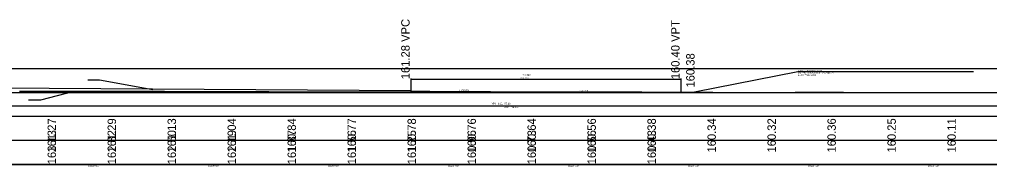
# Model space of a CAD drawing. Extents: x 2126510 to 2136144, y 865066 to 868066.
# Drawn here: x 2130187 to 2130996, y 866612 to 866735 of the extents above; entities that cross this region are included whole.
import ezdxf

# ---------------------------------------------------------------- set-up
doc = ezdxf.new("R2010")
doc.units = 0
for name, color, linetype in [('RD_EX_GuardRail', 7, 'Continuous'), ('RD_EX_H2O', 7, 'Continuous'), ('RD_EX_Misc', 7, 'Continuous')]:
    doc.layers.add(name, color=color, linetype=linetype)

msp = doc.modelspace()

# ---------------------------------------------------------------- linework, layer by layer
at = {"layer": 'RD_EX_GuardRail'}
for p, q in [((2131097.7, 866693.9), (2126517.45, 866693.9)), ((2131097.7, 866673.9), (2129000.13, 866673.9)), ((2131097.7, 866653.9), (2126517.45, 866653.9)), ((2131097.7, 866633.9), (2126517.45, 866633.9)), ((2131097.7, 866613.9), (2126517.45, 866613.9))]:
    msp.add_line(p, q, dxfattribs=at)
at = {"layer": 'RD_EX_H2O'}
for points in [[(2130187.19, 866675.18), (2130188.19, 866675.19), (2130189.19, 866675.19), (2130190.19, 866675.19), (2130191.19, 866675.18), (2130192.19, 866675.18), (2130193.19, 866675.18), (2130194.19, 866675.17), (2130195.19, 866675.17), (2130196.19, 866675.17), (2130197.19, 866675.17), (2130198.19, 866675.17), (2130199.19, 866675.17), (2130200.19, 866675.16), (2130201.19, 866675.16), (2130202.19, 866675.16), (2130203.19, 866675.16), (2130204.19, 866675.16), (2130205.19, 866675.16), (2130206.19, 866675.16), (2130207.19, 866675.16), (2130208.19, 866675.16), (2130209.19, 866675.16), (2130210.19, 866675.16), (2130211.19, 866675.16), (2130212.19, 866675.17), (2130213.19, 866675.17), (2130214.19, 866675.17), (2130215.19, 866675.17), (2130216.19, 866675.17), (2130217.19, 866675.17), (2130218.19, 866675.17), (2130219.19, 866675.17), (2130220.19, 866675.17), (2130221.19, 866675.17), (2130222.19, 866675.17), (2130223.19, 866675.17), (2130224.19, 866675.17), (2130225.19, 866675.17), (2130226.19, 866675.17), (2130227.19, 866675.18), (2130228.19, 866675.18), (2130229.19, 866675.18), (2130230.19, 866675.18), (2130231.19, 866675.18), (2130232.19, 866675.18)], [(2130232.19, 866675.18), (2130233.19, 866675.18), (2130234.19, 866675.18), (2130235.19, 866675.19), (2130236.19, 866675.19), (2130237.19, 866675.19), (2130238.19, 866675.19), (2130239.19, 866675.19), (2130240.19, 866675.19), (2130241.19, 866675.19), (2130242.19, 866675.2), (2130243.19, 866675.2), (2130244.19, 866675.2), (2130245.19, 866675.2), (2130246.19, 866675.2), (2130247.19, 866675.2), (2130248.19, 866675.21), (2130249.19, 866675.21), (2130250.19, 866675.21), (2130251.19, 866675.21), (2130252.19, 866675.21), (2130253.19, 866675.21), (2130254.19, 866675.21), (2130255.19, 866675.21), (2130256.19, 866675.21), (2130257.19, 866675.21), (2130258.19, 866675.21), (2130259.19, 866675.21), (2130260.19, 866675.21), (2130261.19, 866675.2), (2130262.19, 866675.2), (2130263.19, 866675.2), (2130264.19, 866675.2), (2130265.19, 866675.2), (2130266.19, 866675.2), (2130267.19, 866675.2), (2130268.19, 866675.2), (2130269.19, 866675.19), (2130270.19, 866675.19), (2130271.19, 866675.19), (2130272.19, 866675.19), (2130273.19, 866675.19), (2130274.19, 866675.19), (2130275.19, 866675.19), (2130276.19, 866675.18), (2130277.19, 866675.18), (2130278.19, 866675.18), (2130279.19, 866675.18), (2130280.19, 866675.18), (2130281.19, 866675.18), (2130282.19, 866675.17), (2130283.19, 866675.17), (2130284.19, 866675.17), (2130285.19, 866675.17), (2130286.19, 866675.17), (2130287.19, 866675.17), (2130288.19, 866675.17), (2130289.19, 866675.16), (2130290.19, 866675.16), (2130291.19, 866675.16), (2130292.19, 866675.16), (2130293.19, 866675.16), (2130294.19, 866675.16), (2130295.19, 866675.15), (2130296.19, 866675.15), (2130297.19, 866675.15), (2130298.19, 866675.15), (2130299.19, 866675.14), (2130300.19, 866675.14), (2130301.19, 866675.14), (2130302.19, 866675.13), (2130303.19, 866675.13), (2130304.19, 866675.12), (2130305.19, 866675.11), (2130306.19, 866675.1), (2130307.19, 866675.1), (2130308.19, 866675.09), (2130309.19, 866675.08), (2130310.19, 866675.08), (2130311.19, 866675.07), (2130312.19, 866675.06), (2130313.19, 866675.06), (2130314.19, 866675.05), (2130315.19, 866675.05), (2130316.19, 866675.04), (2130317.19, 866675.04), (2130318.19, 866675.04), (2130319.19, 866675.04), (2130320.19, 866675.04), (2130321.19, 866675.03), (2130322.19, 866675.03), (2130323.19, 866675.03), (2130324.19, 866675.03), (2130325.19, 866675.03), (2130326.19, 866675.03), (2130327.19, 866675.03), (2130328.19, 866675.02), (2130329.19, 866675.02), (2130330.19, 866675.02), (2130331.19, 866675.02), (2130332.19, 866675.02)], [(2130332.19, 866675.02), (2130333.19, 866675.02), (2130334.19, 866675.02), (2130335.19, 866675.02), (2130336.19, 866675.02), (2130337.19, 866675.02), (2130338.19, 866675.02), (2130339.19, 866675.02), (2130340.19, 866675.02), (2130341.19, 866675.02), (2130342.19, 866675.02), (2130343.19, 866675.02), (2130344.19, 866675.02), (2130345.19, 866675.02), (2130346.19, 866675.01), (2130347.19, 866675.01), (2130348.19, 866675.01), (2130349.19, 866675.01), (2130350.19, 866675.01), (2130351.19, 866675.01), (2130352.19, 866675.01), (2130353.19, 866675.01), (2130354.19, 866675.01), (2130355.19, 866675.01), (2130356.19, 866675), (2130357.19, 866675), (2130358.19, 866674.99), (2130359.19, 866674.99), (2130360.19, 866674.98), (2130361.19, 866674.98), (2130362.19, 866674.97), (2130363.19, 866674.97), (2130364.19, 866674.96), (2130365.19, 866674.96), (2130366.19, 866674.95), (2130367.19, 866674.95), (2130368.19, 866674.94), (2130369.19, 866674.94), (2130370.19, 866674.93), (2130371.19, 866674.93), (2130372.19, 866674.92), (2130373.19, 866674.92), (2130374.19, 866674.91), (2130375.19, 866674.91), (2130376.19, 866674.9), (2130377.19, 866674.9), (2130378.19, 866674.89), (2130379.19, 866674.89), (2130380.19, 866674.88), (2130381.19, 866674.88), (2130382.19, 866674.87), (2130383.19, 866674.87), (2130384.19, 866674.86), (2130385.19, 866674.86), (2130386.19, 866674.85), (2130387.19, 866674.85), (2130388.19, 866674.84), (2130389.19, 866674.84), (2130390.19, 866674.83), (2130391.19, 866674.83), (2130392.19, 866674.82), (2130393.19, 866674.82), (2130394.19, 866674.81), (2130395.19, 866674.81), (2130396.19, 866674.8), (2130397.19, 866674.8), (2130398.19, 866674.8), (2130399.19, 866674.8), (2130400.19, 866674.79), (2130401.19, 866674.79), (2130402.19, 866674.79), (2130403.19, 866674.79), (2130404.19, 866674.79), (2130405.19, 866674.78), (2130406.19, 866674.78), (2130407.19, 866674.78), (2130408.19, 866674.78), (2130409.19, 866674.77), (2130410.19, 866674.77), (2130411.19, 866674.77), (2130412.19, 866674.77), (2130413.19, 866674.76), (2130414.19, 866674.76), (2130415.19, 866674.76), (2130416.19, 866674.76), (2130417.19, 866674.75), (2130418.19, 866674.75), (2130419.19, 866674.75), (2130420.19, 866674.74), (2130421.19, 866674.74), (2130422.19, 866674.74), (2130423.19, 866674.73), (2130424.19, 866674.73), (2130425.19, 866674.73), (2130426.19, 866674.72), (2130427.19, 866674.72), (2130428.19, 866674.72), (2130429.19, 866674.71), (2130430.19, 866674.71), (2130431.19, 866674.71), (2130432.19, 866674.7)], [(2130432.19, 866674.7), (2130433.19, 866674.7), (2130434.19, 866674.7), (2130435.19, 866674.7), (2130436.19, 866674.7), (2130437.19, 866674.7), (2130438.19, 866674.7), (2130439.19, 866674.7), (2130440.19, 866674.7), (2130441.19, 866674.7), (2130442.19, 866674.69), (2130443.19, 866674.69), (2130444.19, 866674.69), (2130445.19, 866674.69), (2130446.19, 866674.69), (2130447.19, 866674.69), (2130448.19, 866674.69), (2130449.19, 866674.69), (2130450.19, 866674.69), (2130451.19, 866674.69), (2130452.19, 866674.69), (2130453.19, 866674.69), (2130454.19, 866674.68), (2130455.19, 866674.68), (2130456.19, 866674.68), (2130457.19, 866674.68), (2130458.19, 866674.68), (2130459.19, 866674.68), (2130460.19, 866674.68), (2130461.19, 866674.68), (2130462.19, 866674.68), (2130463.19, 866674.68), (2130464.19, 866674.67), (2130465.19, 866674.67), (2130466.19, 866674.67), (2130467.19, 866674.67), (2130468.19, 866674.67), (2130469.19, 866674.67), (2130470.19, 866674.67), (2130471.19, 866674.67), (2130472.19, 866674.67), (2130473.19, 866674.67), (2130474.19, 866674.67), (2130475.19, 866674.67), (2130476.19, 866674.67), (2130477.19, 866674.67), (2130478.19, 866674.67), (2130479.19, 866674.67), (2130480.19, 866674.67), (2130481.19, 866674.67), (2130482.19, 866674.67), (2130483.19, 866674.67), (2130484.19, 866674.68), (2130485.19, 866674.68), (2130486.19, 866674.68), (2130487.19, 866674.68), (2130488.19, 866674.68), (2130489.19, 866674.68), (2130490.19, 866674.68), (2130491.19, 866674.68), (2130492.19, 866674.68), (2130493.19, 866674.68), (2130494.19, 866674.68), (2130495.19, 866674.68), (2130496.19, 866674.68), (2130497.19, 866674.68), (2130498.19, 866674.68), (2130499.19, 866674.68), (2130500.19, 866674.68), (2130501.19, 866674.68), (2130502.19, 866674.68), (2130503.19, 866674.68), (2130504.19, 866674.68), (2130505.19, 866674.68), (2130506.19, 866674.68), (2130507.19, 866674.68), (2130508.19, 866674.68), (2130509.19, 866674.68), (2130510.19, 866674.68), (2130511.19, 866674.68), (2130512.19, 866674.68), (2130513.19, 866674.68), (2130514.19, 866674.68), (2130515.19, 866674.69), (2130516.19, 866674.69), (2130517.19, 866674.69), (2130518.19, 866674.69), (2130519.19, 866674.69), (2130520.19, 866674.69), (2130521.19, 866674.69), (2130522.19, 866674.69), (2130523.19, 866674.69), (2130524.19, 866674.69), (2130525.19, 866674.69), (2130526.19, 866674.69), (2130527.19, 866674.69), (2130528.19, 866674.69), (2130529.19, 866674.69), (2130530.19, 866674.69), (2130531.19, 866674.69), (2130532.19, 866674.69)], [(2130532.19, 866674.69), (2130533.19, 866674.69), (2130534.19, 866674.69), (2130535.19, 866674.69), (2130536.19, 866674.69), (2130537.19, 866674.69), (2130538.19, 866674.69), (2130539.19, 866674.7), (2130540.19, 866674.7), (2130541.19, 866674.7), (2130542.19, 866674.7), (2130543.19, 866674.7), (2130544.19, 866674.7), (2130545.19, 866674.7), (2130546.19, 866674.7), (2130547.19, 866674.7), (2130548.19, 866674.7), (2130549.19, 866674.7), (2130550.19, 866674.7), (2130551.19, 866674.7), (2130552.19, 866674.69), (2130553.19, 866674.69), (2130554.19, 866674.69), (2130555.19, 866674.69), (2130556.19, 866674.69), (2130557.19, 866674.68), (2130558.19, 866674.68), (2130559.19, 866674.68), (2130560.19, 866674.68), (2130561.19, 866674.68), (2130562.19, 866674.68), (2130563.19, 866674.67), (2130564.19, 866674.67), (2130565.19, 866674.67), (2130566.19, 866674.67), (2130567.19, 866674.67), (2130568.19, 866674.66), (2130569.19, 866674.66), (2130570.19, 866674.66), (2130571.19, 866674.66), (2130572.19, 866674.66), (2130573.19, 866674.65), (2130574.19, 866674.65), (2130575.19, 866674.65), (2130576.19, 866674.64), (2130577.19, 866674.64), (2130578.19, 866674.63), (2130579.19, 866674.63), (2130580.19, 866674.63), (2130581.19, 866674.62), (2130582.19, 866674.62), (2130583.19, 866674.61), (2130584.19, 866674.61), (2130585.19, 866674.6), (2130586.19, 866674.6), (2130587.19, 866674.6), (2130588.19, 866674.59), (2130589.19, 866674.59), (2130590.19, 866674.59), (2130591.19, 866674.58), (2130592.19, 866674.58), (2130593.19, 866674.58), (2130594.19, 866674.58), (2130595.19, 866674.58), (2130596.19, 866674.58), (2130597.19, 866674.57), (2130598.19, 866674.57), (2130599.19, 866674.57), (2130600.19, 866674.57), (2130601.19, 866674.57), (2130602.19, 866674.57), (2130603.19, 866674.57), (2130604.19, 866674.56), (2130605.19, 866674.56), (2130606.19, 866674.56), (2130607.19, 866674.56), (2130608.19, 866674.56), (2130609.19, 866674.56), (2130610.19, 866674.55), (2130611.19, 866674.55), (2130612.19, 866674.55), (2130613.19, 866674.55), (2130614.19, 866674.55), (2130615.19, 866674.55), (2130616.19, 866674.55), (2130617.19, 866674.54), (2130618.19, 866674.54), (2130619.19, 866674.54), (2130620.19, 866674.54), (2130621.19, 866674.54), (2130622.19, 866674.54), (2130623.19, 866674.53), (2130624.19, 866674.53), (2130625.19, 866674.53), (2130626.19, 866674.53), (2130627.19, 866674.53), (2130628.19, 866674.53), (2130629.19, 866674.52), (2130630.19, 866674.52), (2130631.19, 866674.52), (2130632.19, 866674.52)]]:
    msp.add_lwpolyline(points, dxfattribs=at)
at = {"layer": 'RD_EX_Misc'}
for p, q in [((2130982.54, 866691.4), (2130835.93, 866691.4)), ((2129494.88, 866682.29), (2130513.48, 866675.88)), ((2130513.48, 866685.68), (2130513.48, 866675.18)), ((2130513.48, 866685.18), (2130738.48, 866685.18)), ((2130738.48, 866685.68), (2130738.48, 866674.3)), ((2130546.02, 866674.98), (2130625.98, 866674.47)), ((2130705.98, 866674.35), (2130625.98, 866674.47)), ((2130738.48, 866674.3), (2130749.98, 866674.29)), ((2127368.72, 866613.9), (2131522.97, 866613.9))]:
    msp.add_line(p, q, dxfattribs=at)
for points in [[(2130835.93, 866691.4), (2130749.97, 866674.29)], [(2130244.17, 866684.73), (2130254.11, 866684.73), (2130298.38, 866676.54)], [(2130194.89, 866668.11), (2130205.08, 866668.11), (2130232.85, 866675.18)], [(2130632.19, 866674.52), (2130633.19, 866674.52), (2130634.19, 866674.51), (2130635.19, 866674.51), (2130636.19, 866674.51), (2130637.19, 866674.51), (2130638.19, 866674.5), (2130639.19, 866674.5), (2130640.19, 866674.5), (2130641.19, 866674.5), (2130642.19, 866674.49), (2130643.19, 866674.49), (2130644.19, 866674.49), (2130645.19, 866674.49), (2130646.19, 866674.49), (2130647.19, 866674.48), (2130648.19, 866674.48), (2130649.19, 866674.48), (2130650.19, 866674.48), (2130651.19, 866674.47), (2130652.19, 866674.47), (2130653.19, 866674.47), (2130654.19, 866674.47), (2130655.19, 866674.47), (2130656.19, 866674.47), (2130657.19, 866674.47), (2130658.19, 866674.47), (2130659.19, 866674.47), (2130660.19, 866674.47), (2130661.19, 866674.47), (2130662.19, 866674.46), (2130663.19, 866674.46), (2130664.19, 866674.46), (2130665.19, 866674.46), (2130666.19, 866674.46), (2130667.19, 866674.46), (2130668.19, 866674.46), (2130669.19, 866674.46), (2130670.19, 866674.46), (2130671.19, 866674.46), (2130672.19, 866674.45), (2130673.19, 866674.45), (2130674.19, 866674.44), (2130675.19, 866674.44), (2130676.19, 866674.43), (2130677.19, 866674.43), (2130678.19, 866674.42), (2130679.19, 866674.42), (2130680.19, 866674.41), (2130681.19, 866674.41), (2130682.19, 866674.4), (2130683.19, 866674.4), (2130684.19, 866674.39), (2130685.19, 866674.39), (2130686.19, 866674.38), (2130687.19, 866674.38), (2130688.19, 866674.38), (2130689.19, 866674.37), (2130690.19, 866674.37), (2130691.19, 866674.36), (2130692.19, 866674.36), (2130693.19, 866674.35), (2130694.19, 866674.35), (2130695.19, 866674.34), (2130696.19, 866674.34), (2130697.19, 866674.33), (2130698.19, 866674.33), (2130699.19, 866674.32), (2130700.19, 866674.32), (2130701.19, 866674.31), (2130702.19, 866674.31), (2130703.19, 866674.31), (2130704.19, 866674.3), (2130705.19, 866674.3), (2130706.19, 866674.29), (2130707.19, 866674.29), (2130708.19, 866674.28), (2130709.19, 866674.28), (2130710.19, 866674.27), (2130711.19, 866674.27), (2130712.19, 866674.27), (2130713.19, 866674.27), (2130714.19, 866674.28), (2130715.19, 866674.28), (2130716.19, 866674.28), (2130717.19, 866674.28), (2130718.19, 866674.28), (2130719.19, 866674.28), (2130720.19, 866674.28), (2130721.19, 866674.28), (2130722.19, 866674.29), (2130723.19, 866674.29), (2130724.19, 866674.29), (2130725.19, 866674.29), (2130726.19, 866674.29), (2130727.19, 866674.29), (2130728.19, 866674.29), (2130729.19, 866674.29), (2130730.19, 866674.3), (2130731.19, 866674.29), (2130732.19, 866674.29)], [(2130732.19, 866674.29), (2130733.19, 866674.29), (2130734.19, 866674.29), (2130735.19, 866674.29), (2130736.19, 866674.29), (2130737.19, 866674.29), (2130738.19, 866674.29), (2130739.19, 866674.29), (2130740.19, 866674.29), (2130741.19, 866674.29), (2130742.19, 866674.29), (2130743.19, 866674.29), (2130744.19, 866674.29), (2130745.19, 866674.29), (2130746.19, 866674.29), (2130747.19, 866674.29), (2130748.19, 866674.29), (2130749.19, 866674.29), (2130750.19, 866674.29), (2130751.19, 866674.28), (2130752.19, 866674.28), (2130753.19, 866674.28), (2130754.19, 866674.28), (2130755.19, 866674.27), (2130756.19, 866674.27), (2130757.19, 866674.27), (2130758.19, 866674.26), (2130759.19, 866674.26), (2130760.19, 866674.26), (2130761.19, 866674.26), (2130762.19, 866674.25), (2130763.19, 866674.25), (2130764.19, 866674.25), (2130765.19, 866674.25), (2130766.19, 866674.24), (2130767.19, 866674.24), (2130768.19, 866674.24), (2130769.19, 866674.24), (2130770.19, 866674.23), (2130771.19, 866674.23), (2130772.19, 866674.23), (2130773.19, 866674.23), (2130774.19, 866674.22), (2130775.19, 866674.22), (2130776.19, 866674.22), (2130777.19, 866674.22), (2130778.19, 866674.21), (2130779.19, 866674.21), (2130780.19, 866674.21), (2130781.19, 866674.21), (2130782.19, 866674.2), (2130783.19, 866674.2), (2130784.19, 866674.2), (2130785.19, 866674.2), (2130786.19, 866674.19), (2130787.19, 866674.19), (2130788.19, 866674.19), (2130789.19, 866674.2), (2130790.19, 866674.2), (2130791.19, 866674.2), (2130792.19, 866674.2), (2130793.19, 866674.2), (2130794.19, 866674.2), (2130795.19, 866674.2), (2130796.19, 866674.2), (2130797.19, 866674.2), (2130798.19, 866674.2), (2130799.19, 866674.2), (2130800.19, 866674.2), (2130801.19, 866674.2), (2130802.19, 866674.2), (2130803.19, 866674.2), (2130804.19, 866674.2), (2130805.19, 866674.2), (2130806.19, 866674.2), (2130807.19, 866674.2), (2130808.19, 866674.2), (2130809.19, 866674.21), (2130810.19, 866674.21), (2130811.19, 866674.21), (2130812.19, 866674.21), (2130813.19, 866674.21), (2130814.19, 866674.21), (2130815.19, 866674.22), (2130816.19, 866674.22), (2130817.19, 866674.22), (2130818.19, 866674.22), (2130819.19, 866674.22), (2130820.19, 866674.23), (2130821.19, 866674.23), (2130822.19, 866674.23), (2130823.19, 866674.23), (2130824.19, 866674.23), (2130825.19, 866674.24), (2130826.19, 866674.24), (2130827.19, 866674.24), (2130828.19, 866674.24), (2130829.19, 866674.24), (2130830.19, 866674.24), (2130831.19, 866674.24), (2130832.19, 866674.24)], [(2130832.19, 866674.24), (2130833.19, 866674.24), (2130834.19, 866674.25), (2130835.19, 866674.25), (2130836.19, 866674.25), (2130837.19, 866674.25), (2130838.19, 866674.25), (2130839.19, 866674.25), (2130840.19, 866674.25), (2130841.19, 866674.25), (2130842.19, 866674.25), (2130843.19, 866674.25), (2130844.19, 866674.25), (2130845.19, 866674.26), (2130846.19, 866674.26), (2130847.19, 866674.26), (2130848.19, 866674.26), (2130849.19, 866674.26), (2130850.19, 866674.26), (2130851.19, 866674.26), (2130852.19, 866674.26), (2130853.19, 866674.26), (2130854.19, 866674.26), (2130855.19, 866674.27), (2130856.19, 866674.27), (2130857.19, 866674.27), (2130858.19, 866674.27), (2130859.19, 866674.27), (2130860.19, 866674.27), (2130861.19, 866674.27), (2130862.19, 866674.27), (2130863.19, 866674.27), (2130864.19, 866674.27), (2130865.19, 866674.27), (2130866.19, 866674.28), (2130867.19, 866674.27), (2130868.19, 866674.27), (2130869.19, 866674.27), (2130870.19, 866674.26), (2130871.19, 866674.26), (2130872.19, 866674.25), (2130873.19, 866674.25), (2130874.19, 866674.25), (2130875.19, 866674.24), (2130876.19, 866674.24), (2130877.19, 866674.24), (2130878.19, 866674.23), (2130879.19, 866674.23), (2130880.19, 866674.22), (2130881.19, 866674.22), (2130882.19, 866674.22), (2130883.19, 866674.21), (2130884.19, 866674.21), (2130885.19, 866674.21), (2130886.19, 866674.2), (2130887.19, 866674.2), (2130888.19, 866674.2), (2130889.19, 866674.19), (2130890.19, 866674.19), (2130891.19, 866674.19), (2130892.19, 866674.19), (2130893.19, 866674.18), (2130894.19, 866674.18), (2130895.19, 866674.18), (2130896.19, 866674.18), (2130897.19, 866674.18), (2130898.19, 866674.18), (2130899.19, 866674.18), (2130900.19, 866674.17), (2130901.19, 866674.17), (2130902.19, 866674.17), (2130903.19, 866674.17), (2130904.19, 866674.17), (2130905.19, 866674.17), (2130906.19, 866674.17), (2130907.19, 866674.16), (2130908.19, 866674.16), (2130909.19, 866674.16), (2130910.19, 866674.16), (2130911.19, 866674.16), (2130912.19, 866674.16), (2130913.19, 866674.16), (2130914.19, 866674.15), (2130915.19, 866674.15), (2130916.19, 866674.15), (2130917.19, 866674.15), (2130918.19, 866674.15), (2130919.19, 866674.15), (2130920.19, 866674.15), (2130921.19, 866674.15), (2130922.19, 866674.15), (2130923.19, 866674.14), (2130924.19, 866674.14), (2130925.19, 866674.14), (2130926.19, 866674.14), (2130927.19, 866674.14), (2130928.19, 866674.14), (2130929.19, 866674.14), (2130930.19, 866674.14), (2130931.19, 866674.14), (2130932.19, 866674.13)], [(2130932.19, 866674.13), (2130933.19, 866674.13), (2130934.19, 866674.13), (2130935.19, 866674.13), (2130936.19, 866674.13), (2130937.19, 866674.13), (2130938.19, 866674.13), (2130939.19, 866674.13), (2130940.19, 866674.13), (2130941.19, 866674.12), (2130942.19, 866674.12), (2130943.19, 866674.12), (2130944.19, 866674.12), (2130945.19, 866674.12), (2130946.19, 866674.12), (2130947.19, 866674.11), (2130948.19, 866674.11), (2130949.19, 866674.1), (2130950.19, 866674.1), (2130951.19, 866674.09), (2130952.19, 866674.09), (2130953.19, 866674.08), (2130954.19, 866674.08), (2130955.19, 866674.07), (2130956.19, 866674.07), (2130957.19, 866674.06), (2130958.19, 866674.06), (2130959.19, 866674.05), (2130960.19, 866674.05), (2130961.19, 866674.04), (2130962.19, 866674.04), (2130963.19, 866674.03), (2130964.19, 866674.03), (2130965.19, 866674.02), (2130966.19, 866674.02), (2130967.19, 866674.01), (2130968.19, 866674.01), (2130969.19, 866674.01), (2130970.19, 866674.01), (2130971.19, 866674.01), (2130972.19, 866674.01), (2130973.19, 866674.01), (2130974.19, 866674.01), (2130975.19, 866674.01), (2130976.19, 866674.01), (2130977.19, 866674.01), (2130978.19, 866674.01), (2130979.19, 866674.01), (2130980.19, 866674.01), (2130981.19, 866674.01), (2130982.19, 866674.01), (2130983.19, 866674.01), (2130984.19, 866674.01), (2130985.19, 866674.01), (2130986.19, 866674.01), (2130987.19, 866674.02), (2130988.19, 866674.02), (2130989.19, 866674.02), (2130990.19, 866674.02), (2130991.19, 866674.02), (2130992.19, 866674.02), (2130993.19, 866674.02), (2130994.19, 866674.02), (2130995.19, 866674.02), (2130996.19, 866674.03)], [(2127275.85, 866613.9), (2127275.85, 866662.9), (2131989.68, 866662.9)]]:
    msp.add_lwpolyline(points, dxfattribs=at)
msp.add_spline([(2130513.48, 866675.18), (2130517.98, 866675.15), (2130522.48, 866675.12), (2130526.98, 866675.1), (2130531.48, 866675.07), (2130535.98, 866675.04), (2130540.48, 866675.02), (2130544.98, 866674.99), (2130549.48, 866674.97), (2130553.98, 866674.94), (2130558.48, 866674.92), (2130562.98, 866674.89), (2130567.48, 866674.87), (2130571.98, 866674.85), (2130576.48, 866674.83), (2130580.98, 866674.8), (2130585.48, 866674.78), (2130589.98, 866674.76), (2130594.48, 866674.74), (2130598.98, 866674.72), (2130603.48, 866674.7), (2130607.98, 866674.68), (2130612.48, 866674.66), (2130616.98, 866674.64), (2130621.48, 866674.62), (2130625.98, 866674.61), (2130630.48, 866674.59), (2130634.98, 866674.57), (2130639.48, 866674.56), (2130643.98, 866674.54), (2130648.48, 866674.52), (2130652.98, 866674.51), (2130657.48, 866674.49), (2130661.98, 866674.48), (2130666.48, 866674.47), (2130670.98, 866674.45), (2130675.48, 866674.44), (2130679.98, 866674.43), (2130684.48, 866674.42), (2130688.98, 866674.4), (2130693.48, 866674.39), (2130697.98, 866674.38), (2130702.48, 866674.37), (2130706.98, 866674.36), (2130711.48, 866674.35), (2130715.98, 866674.34), (2130720.48, 866674.33), (2130724.98, 866674.33), (2130729.48, 866674.32), (2130733.98, 866674.31), (2130738.48, 866674.3)], degree=3, dxfattribs=at)

# ---------------------------------------------------------------- texts
for s, height, rotation, p in [('161.28 VPC', 7, 90, (2130512.48, 866685.18)), ('160.40 VPT', 7, 90, (2130737.48, 866685.18)), ('160.38', 7, 90, (2130749.98, 866678.29)), ('(-) 0.63%', 1.417, 359.63913, (2130553.76, 866675.33)), ('(-) 0.15%', 1.401, 359.91406, (2130653.67, 866674.83)), ('161.27', 7, 90, (2130217.72, 866623.9)), ('161.29', 7, 90, (2130267.72, 866623.9)), ('161.13', 7, 90, (2130317.72, 866623.9)), ('161.04', 7, 90, (2130367.72, 866623.9)), ('160.84', 7, 90, (2130417.72, 866623.9)), ('160.77', 7, 90, (2130467.72, 866623.9)), ('160.78', 7, 90, (2130517.72, 866623.9)), ('160.76', 7, 90, (2130567.72, 866623.9)), ('160.64', 7, 90, (2130617.72, 866623.9)), ('160.56', 7, 90, (2130667.72, 866623.9)), ('160.38', 7, 90, (2130717.72, 866623.9)), ('160.34', 7, 90, (2130767.72, 866623.9)), ('160.32', 7, 90, (2130817.72, 866623.9)), ('160.36', 7, 90, (2130867.72, 866623.9)), ('160.25', 7, 90, (2130917.72, 866623.9)), ('160.11', 7, 90, (2130967.72, 866623.9)), ('163.13', 7, 90, (2130217.72, 866614.05)), ('162.82', 7, 90, (2130267.72, 866614.05)), ('162.50', 7, 90, (2130317.72, 866614.05)), ('162.19', 7, 90, (2130367.72, 866614.05)), ('161.87', 7, 90, (2130417.72, 866614.05)), ('161.56', 7, 90, (2130467.72, 866614.05)), ('161.25', 7, 90, (2130517.72, 866614.05)), ('160.96', 7, 90, (2130567.72, 866614.05)), ('160.73', 7, 90, (2130617.72, 866614.05)), ('160.56', 7, 90, (2130667.72, 866614.05)), ('160.43', 7, 90, (2130717.72, 866614.05))]:
    msp.add_text(s, height=height, rotation=rotation, dxfattribs=at).set_placement(p)
for s, height, p in [("225' V.C.", 1.4, (2130604.72, 866685.43)), ('K = 469', 1.4, (2130606.42, 866688.23)), ('END CONSTRUCTION', 1.4, (2130836.09, 866691.6)), ('ELEV = 160.3833', 1.4, (2130836.09, 866688)), ('I20_EB_CONST STA. 1822+81.25', 1.4, (2130836.09, 866689.8)), ('VPI = 1821+57.26', 1.4, (2130580.91, 866664.07)), ('Elev. = 160.57', 1.4, (2130590.92, 866661.07)), ('1818+00', 1.6, (2130244.51, 866612.1)), ('1819+00', 1.6, (2130344.51, 866612.1)), ('1820+00', 1.6, (2130444.51, 866612.1)), ('1821+00', 1.6, (2130544.51, 866612.1)), ('1822+00', 1.6, (2130644.51, 866612.1)), ('1823+00', 1.6, (2130744.51, 866612.1)), ('1824+00', 1.6, (2130844.51, 866612.1)), ('1825+00', 1.6, (2130944.51, 866612.1))]:
    msp.add_text(s, height=height, dxfattribs=at).set_placement(p)

doc.saveas('drawing.dxf')
